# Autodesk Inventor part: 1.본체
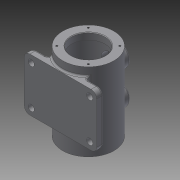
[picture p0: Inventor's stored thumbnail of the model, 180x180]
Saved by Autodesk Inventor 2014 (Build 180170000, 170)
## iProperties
Created: 2014-12
Part Number: 1.본체
Material: 일반
Document SubType Name: Modeling
Designer: Owner
Density: 1 g/cm^3
Appearance: 기본값
Author: Owner
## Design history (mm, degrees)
sketch "스케치1"
  geometry: C1 r 46 at (0, 0); 1 further point
  constraints: 1 centre point, 1 coincident
  dimensions: "d0" = 92 diameter of C1
extrude "돌출1" new body sketch "스케치1" stored distance "d1" = 140; taper "d2" = 0 deg
node "작업 평면1"
sketch "스케치2"
  geometry: L1 (-65, -40)-(65, -40); L2 (65, -40)-(65, 55); L3 (65, 55)-(-65, 55); L4 (-65, 55)-(-65, -40); L5 (46, 70)-(-46, 70) reference; 1 further point
  constraints: 8 end point, 2 parallel, 1 horizontal, 1 perpendicular
  dimensions: "d4" = 130 distance between parallel lines of L2 L4; "d5" = 65 distance from line of L4 point (0, 0); "d6" = 95 distance between parallel lines of L3 L1; "d7" = 15 distance between parallel lines of L5 L3
extrude "돌출2" join sketch "스케치2" distance "d8" = 12; taper "d9" = 0 deg
node "작업 평면2"
sketch "스케치3"
  geometry: L1 (-46, -70)-(46, -70) reference; L2 (46, 70)-(-46, 70) reference; C1 r 20 at (0, -30); C2 r 20 at (0, 30); 1 further point
  constraints: 2 centre point, 1 vertical alignment
  dimensions: "d11" = 40 diameter of C1; "d12" = 40 diameter of C2; "d13" = 40 distance from line of L1 C1.centre; "d14" = 60 distance of C2.centre C1.centre; "d15" = 40 distance from line of L2 C2.centre
extrude "돌출3" join sketch "스케치3" stored distance "d16" = 12; taper "d17" = 0 deg
node "작업 평면3"
sketch "스케치4"
  geometry: L1 (65, 55)-(-65, 55) reference; L2 (-65, -40)-(65, -40) reference; L3 (65, -40)-(65, 55) reference; L4 (-65, 55)-(-65, -40) reference; C1 r 5.5 at (-52.5, -27.5); C2 r 5.5 at (-52.5, 42.5); C3 r 5.5 at (52.5, 42.5); C4 r 5.5 at (52.5, -27.5); 1 further point
  constraints: 4 centre point, 3 equal radius, 2 horizontal alignment, 2 vertical alignment
  dimensions: "d19" = 11 diameter of C1; "d20" = 12.5 distance from line of L1 C3.centre; "d21" = 12.5 distance from line of L2 C1.centre; "d22" = 12.5 distance from line of L3 C4.centre; "d23" = 12.5 distance from line of L4 C1.centre
extrude "돌출4" cut sketch "스케치4" distance "d24" = 12; taper "d25" = 0 deg
sketch "스케치5"
  geometry: L1 (46, 70)-(-46, 70) reference; L2 (-46, -70)-(46, -70) reference; L3 (0, 70)-(0, -70); L4 (30, 70)-(30, 58); L5 (30, 58)-(37.5, 58); L6 (37.5, 58)-(37.5, -58); L7 (37.5, -58)-(30, -58); L8 (30, -58)-(30, -70); L9 (30, 70)-(0, 70); L10 (30, -70)-(0, -70); 1 further point
  constraints: 16 end point, 3 collinear, 3 parallel, 2 midpoint, 2 point on line, 1 perpendicular
  dimensions: "d26" = 12 distance between parallel lines of L9 L5; "d27" = 12 distance between parallel lines of L2 L7; "d28" = 60 diameter of L4 L3; "d29" = 60 diameter of L8 L3; "d30" = 75 diameter of L6 L3
revolve "회전1" sketch "스케치5" stored, may be unused: angle "d31" = 90 deg
fillet "모깎기1" dims "d32" = 10
hole "구멍1" diameter "d35" = 25; stored, may be unused: countersink angle "d39" = 90 deg, drill point angle "d41" = 0 deg; dims "d36" = 6, "d37" = 30, "d38" = 8, "d40" = 25, "d42" = 10, "d43" = 10
hole "구멍2" diameter "d46" = 25; stored, may be unused: countersink angle "d50" = 90 deg, drill point angle "d52" = 0 deg; dims "d47" = 6, "d48" = 30, "d49" = 8, "d51" = 25, "d53" = 10, "d54" = 10
sketch "스케치6" dims "d6" = 95
  geometry: L1 (-65, 30)-(-65, -45) reference; C1 r 5.5 at (-52.5, 27.5) reference; 2 further points
  constraints: 1 other
  dimensions: "d55" = 35 vertical distance of C1.centre point (-57, -7.5); "d56" = 8 distance from line of L1 point (-57, -7.5)
feature "엠보싱1" sketch "스케치6" dims "d18" = -38, "d57" = 1, "d58" = 0
sketch "스케치7"
  geometry: L1 (0, 0)-(28.284, 28.284); L2 (0, 0)-(40, 0); L3 (0, 0)-(-28.284, 28.284); L4 (0, 0)-(-28.284, -28.284); L5 (0, 0)-(28.284, -28.284); C1 r 30 at (0, 0) reference; C2 r 46 at (0, 0) reference; 4 further points
  constraints: 10 end point, 4 coincident, 1 equal length, 1 horizontal, 13 other
  dimensions: "d59" = 40 distance of L1.start L1.end; "d60" = 45 deg angle of L2 L1; "d63" = 360 deg dimension on C1.centre L1.end (derived)
hole "구멍3" sketch "스케치7" at (-28.284, 28.284), (28.284, 28.284), (-28.284, -28.284), (28.284, -28.284) diameter "d65" = 3.242; stored, may be unused: countersink angle "d69" = 90 deg, drill point angle "d71" = 118 deg; dims "d66" = 8, "d67" = 30, "d68" = 8, "d70" = 10
sketch "스케치8"
  geometry: L1 (0, 0)-(28.284, 28.284); L2 (0, 0)-(40, 0); L3 (0, 0)-(-28.284, 28.284); L4 (0, 0)-(-28.284, -28.284); L5 (0, 0)-(28.284, -28.284); C1 r 30 at (0, 0) reference; C2 r 46 at (0, 0) reference; 4 further points
  constraints: 10 end point, 4 coincident, 1 equal length, 1 horizontal, 13 other
  dimensions: "d72" = 40 distance of L1.start L1.end; "d73" = 45 deg angle of L2 L1; "d76" = 360 deg dimension on C1.centre L1.end (derived)
hole "구멍4" sketch "스케치8" at (-28.284, 28.284), (28.284, 28.284), (-28.284, -28.284), (28.284, -28.284) diameter "d78" = 3.242; stored, may be unused: countersink angle "d82" = 90 deg, drill point angle "d84" = 118 deg; dims "d79" = 8, "d80" = 30, "d81" = 8, "d83" = 10
fillet "모깎기2" dims "d85" = 3
chamfer "모따기1" distance "d86" = 1; stored, may be unused: second distance "d87" = 2, angle "d88" = 45 deg
fillet "모깎기3" dims "d89" = 5
fillet "모깎기4" dims "d90" = 3
fillet "모깎기5" dims "d91" = 3
fillet "모깎기6" dims "d92" = 3
node "솔리드1"
other parameters: "d10" = 56
